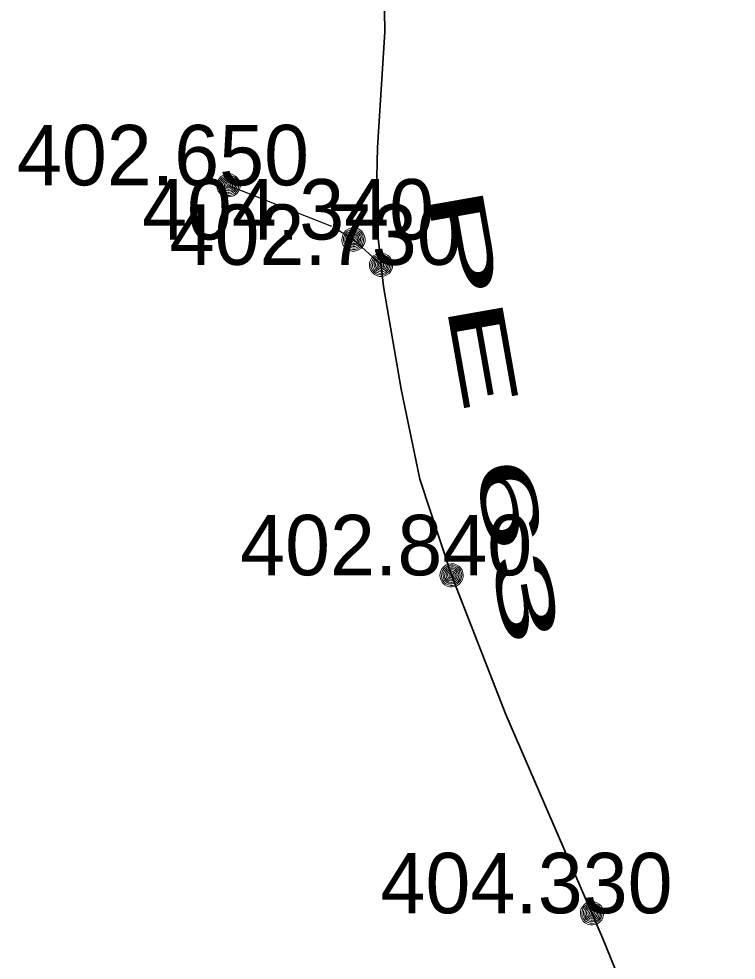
# Model space of a CAD drawing. Extents: x -873619 to -867639, y -1015082 to -1012326.
# Drawn here: x -868003.92 to -867989.67, y -1012758.26 to -1012739.57 of the extents above; entities that cross this region are included whole.
import ezdxf

# ---------------------------------------------------------------- set-up
doc = ezdxf.new("R2010")
doc.units = 0
doc.header["$LTSCALE"] = 0.44
doc.header["$PDMODE"] = 32
doc.header["$PDSIZE"] = 0.22
doc.linetypes.add('DOT_DASHED', pattern=[7.7, 5, -1.2, 0.3, -1.2])
for name, color, linetype, lineweight in [('1', 7, 'Continuous', 13), ('21', 7, 'Continuous', 35), ('23', 7, 'Continuous', 25)]:
    doc.layers.add(name, color=color, linetype=linetype, lineweight=lineweight)
doc.layers.add('33', color=7, linetype='Continuous')

msp = doc.modelspace()

# ---------------------------------------------------------------- linework, layer by layer
at = {"layer": '1'}
for points in [[(-867999.527, -1012742.879), (-867999.534, -1012742.827), (-867999.551, -1012742.777), (-867999.58, -1012742.733), (-867999.617, -1012742.696), (-867999.662, -1012742.669), (-867999.712, -1012742.652), (-867999.765, -1012742.648), (-867999.816, -1012742.655), (-867999.865, -1012742.674), (-867999.909, -1012742.703), (-867999.945, -1012742.742), (-867999.971, -1012742.787), (-867999.987, -1012742.838), (-867999.99, -1012742.89), (-867999.982, -1012742.942), (-867999.962, -1012742.991), (-867999.931, -1012743.034), (-867999.892, -1012743.068), (-867999.846, -1012743.094), (-867999.794, -1012743.108), (-867999.742, -1012743.11), (-867999.691, -1012743.1), (-867999.642, -1012743.079), (-867999.6, -1012743.048), (-867999.566, -1012743.007), (-867999.542, -1012742.961), (-867999.529, -1012742.91)], [(-867999.558, -1012742.879), (-867999.564, -1012742.83), (-867999.581, -1012742.784), (-867999.608, -1012742.744), (-867999.646, -1012742.712), (-867999.69, -1012742.69), (-867999.738, -1012742.679), (-867999.787, -1012742.679), (-867999.833, -1012742.692), (-867999.877, -1012742.716), (-867999.913, -1012742.749), (-867999.94, -1012742.79), (-867999.956, -1012742.837), (-867999.96, -1012742.886), (-867999.953, -1012742.934), (-867999.934, -1012742.979), (-867999.904, -1012743.019), (-867999.865, -1012743.05), (-867999.821, -1012743.07), (-867999.774, -1012743.08), (-867999.725, -1012743.078), (-867999.678, -1012743.063), (-867999.635, -1012743.038), (-867999.6, -1012743.004), (-867999.575, -1012742.962), (-867999.561, -1012742.915)], [(-867999.588, -1012742.879), (-867999.593, -1012742.834), (-867999.61, -1012742.792), (-867999.639, -1012742.757), (-867999.674, -1012742.73), (-867999.717, -1012742.713), (-867999.762, -1012742.708), (-867999.806, -1012742.714), (-867999.848, -1012742.733), (-867999.882, -1012742.761), (-867999.909, -1012742.798), (-867999.926, -1012742.84), (-867999.929, -1012742.885), (-867999.923, -1012742.93), (-867999.904, -1012742.971), (-867999.875, -1012743.005), (-867999.838, -1012743.031), (-867999.794, -1012743.047), (-867999.75, -1012743.05), (-867999.705, -1012743.042), (-867999.664, -1012743.022), (-867999.63, -1012742.993), (-867999.605, -1012742.955), (-867999.591, -1012742.912)], [(-867999.618, -1012742.879), (-867999.622, -1012742.838), (-867999.641, -1012742.801), (-867999.668, -1012742.77), (-867999.703, -1012742.749), (-867999.743, -1012742.738), (-867999.784, -1012742.74), (-867999.823, -1012742.753), (-867999.857, -1012742.777), (-867999.882, -1012742.809), (-867999.897, -1012742.847), (-867999.899, -1012742.888), (-867999.892, -1012742.928), (-867999.872, -1012742.964), (-867999.843, -1012742.993), (-867999.806, -1012743.012), (-867999.766, -1012743.02), (-867999.725, -1012743.016), (-867999.686, -1012743.001), (-867999.654, -1012742.975), (-867999.632, -1012742.941), (-867999.619, -1012742.902)], [(-867999.647, -1012742.879), (-867999.652, -1012742.843), (-867999.671, -1012742.811), (-867999.696, -1012742.786), (-867999.73, -1012742.771), (-867999.767, -1012742.768), (-867999.801, -1012742.776), (-867999.833, -1012742.796), (-867999.855, -1012742.824), (-867999.869, -1012742.858), (-867999.869, -1012742.895), (-867999.858, -1012742.93), (-867999.837, -1012742.959), (-867999.806, -1012742.98), (-867999.772, -1012742.99), (-867999.735, -1012742.988), (-867999.701, -1012742.974), (-867999.674, -1012742.951), (-867999.654, -1012742.919), (-867999.647, -1012742.884)], [(-867999.678, -1012742.879), (-867999.683, -1012742.848), (-867999.7, -1012742.822), (-867999.725, -1012742.805), (-867999.755, -1012742.798), (-867999.787, -1012742.802), (-867999.814, -1012742.819), (-867999.831, -1012742.843), (-867999.84, -1012742.874), (-867999.836, -1012742.904), (-867999.821, -1012742.932), (-867999.796, -1012742.951), (-867999.767, -1012742.96), (-867999.735, -1012742.957), (-867999.708, -1012742.943), (-867999.688, -1012742.919), (-867999.678, -1012742.89)], [(-867999.708, -1012742.879), (-867999.713, -1012742.855), (-867999.73, -1012742.837), (-867999.752, -1012742.828), (-867999.777, -1012742.831), (-867999.798, -1012742.845), (-867999.809, -1012742.867), (-867999.809, -1012742.892), (-867999.796, -1012742.913), (-867999.777, -1012742.927), (-867999.752, -1012742.93), (-867999.728, -1012742.921), (-867999.713, -1012742.903)], [(-867999.738, -1012742.879), (-867999.743, -1012742.864), (-867999.757, -1012742.858), (-867999.772, -1012742.862), (-867999.779, -1012742.876), (-867999.776, -1012742.891), (-867999.762, -1012742.9), (-867999.747, -1012742.897), (-867999.738, -1012742.885)], [(-867997.044, -1012743.954), (-867997.05, -1012743.902), (-867997.067, -1012743.852), (-867997.096, -1012743.808), (-867997.133, -1012743.771), (-867997.178, -1012743.744), (-867997.228, -1012743.727), (-867997.281, -1012743.723), (-867997.333, -1012743.73), (-867997.382, -1012743.749), (-867997.425, -1012743.778), (-867997.461, -1012743.817), (-867997.487, -1012743.862), (-867997.503, -1012743.913), (-867997.506, -1012743.965), (-867997.498, -1012744.017), (-867997.478, -1012744.066), (-867997.447, -1012744.109), (-867997.408, -1012744.143), (-867997.362, -1012744.169), (-867997.311, -1012744.183), (-867997.258, -1012744.185), (-867997.207, -1012744.175), (-867997.159, -1012744.154), (-867997.116, -1012744.123), (-867997.082, -1012744.082), (-867997.058, -1012744.036), (-867997.046, -1012743.985)], [(-867997.074, -1012743.954), (-867997.08, -1012743.905), (-867997.097, -1012743.859), (-867997.125, -1012743.819), (-867997.162, -1012743.787), (-867997.206, -1012743.765), (-867997.254, -1012743.754), (-867997.303, -1012743.754), (-867997.35, -1012743.767), (-867997.393, -1012743.791), (-867997.429, -1012743.824), (-867997.456, -1012743.865), (-867997.472, -1012743.912), (-867997.476, -1012743.961), (-867997.469, -1012744.009), (-867997.45, -1012744.054), (-867997.42, -1012744.094), (-867997.382, -1012744.125), (-867997.338, -1012744.145), (-867997.29, -1012744.155), (-867997.241, -1012744.153), (-867997.194, -1012744.138), (-867997.151, -1012744.113), (-867997.117, -1012744.079), (-867997.091, -1012744.037), (-867997.077, -1012743.99)], [(-867997.104, -1012743.954), (-867997.11, -1012743.909), (-867997.127, -1012743.867), (-867997.155, -1012743.832), (-867997.191, -1012743.805), (-867997.233, -1012743.788), (-867997.278, -1012743.783), (-867997.323, -1012743.789), (-867997.364, -1012743.808), (-867997.399, -1012743.836), (-867997.426, -1012743.873), (-867997.442, -1012743.915), (-867997.446, -1012743.96), (-867997.439, -1012744.005), (-867997.42, -1012744.046), (-867997.391, -1012744.08), (-867997.354, -1012744.106), (-867997.311, -1012744.122), (-867997.266, -1012744.125), (-867997.221, -1012744.117), (-867997.181, -1012744.097), (-867997.147, -1012744.068), (-867997.121, -1012744.03), (-867997.107, -1012743.987)], [(-867997.134, -1012743.954), (-867997.139, -1012743.913), (-867997.157, -1012743.876), (-867997.184, -1012743.845), (-867997.219, -1012743.824), (-867997.259, -1012743.813), (-867997.3, -1012743.815), (-867997.339, -1012743.828), (-867997.373, -1012743.852), (-867997.398, -1012743.884), (-867997.413, -1012743.922), (-867997.416, -1012743.963), (-867997.408, -1012744.003), (-867997.388, -1012744.039), (-867997.359, -1012744.068), (-867997.322, -1012744.087), (-867997.282, -1012744.095), (-867997.241, -1012744.091), (-867997.203, -1012744.076), (-867997.171, -1012744.05), (-867997.148, -1012744.016), (-867997.135, -1012743.977)], [(-867997.164, -1012743.954), (-867997.169, -1012743.918), (-867997.187, -1012743.886), (-867997.213, -1012743.861), (-867997.247, -1012743.846), (-867997.283, -1012743.843), (-867997.318, -1012743.851), (-867997.349, -1012743.871), (-867997.372, -1012743.899), (-867997.385, -1012743.933), (-867997.385, -1012743.97), (-867997.374, -1012744.005), (-867997.353, -1012744.034), (-867997.323, -1012744.055), (-867997.288, -1012744.065), (-867997.251, -1012744.063), (-867997.217, -1012744.049), (-867997.19, -1012744.026), (-867997.171, -1012743.994), (-867997.164, -1012743.959)], [(-867997.194, -1012743.954), (-867997.199, -1012743.923), (-867997.216, -1012743.897), (-867997.242, -1012743.88), (-867997.272, -1012743.873), (-867997.303, -1012743.877), (-867997.33, -1012743.894), (-867997.348, -1012743.918), (-867997.356, -1012743.949), (-867997.352, -1012743.979), (-867997.337, -1012744.007), (-867997.313, -1012744.026), (-867997.283, -1012744.035), (-867997.252, -1012744.032), (-867997.224, -1012744.018), (-867997.204, -1012743.994), (-867997.194, -1012743.965)], [(-867997.224, -1012743.954), (-867997.229, -1012743.93), (-867997.246, -1012743.912), (-867997.269, -1012743.903), (-867997.293, -1012743.906), (-867997.314, -1012743.92), (-867997.325, -1012743.942), (-867997.325, -1012743.967), (-867997.313, -1012743.988), (-867997.293, -1012744.002), (-867997.268, -1012744.005), (-867997.245, -1012743.996), (-867997.229, -1012743.978)], [(-867997.254, -1012743.954), (-867997.259, -1012743.939), (-867997.274, -1012743.933), (-867997.289, -1012743.937), (-867997.296, -1012743.951), (-867997.292, -1012743.966), (-867997.279, -1012743.975), (-867997.264, -1012743.972), (-867997.254, -1012743.96)], [(-867996.495, -1012744.457), (-867996.502, -1012744.405), (-867996.519, -1012744.355), (-867996.548, -1012744.311), (-867996.585, -1012744.274), (-867996.63, -1012744.247), (-867996.679, -1012744.23), (-867996.733, -1012744.226), (-867996.784, -1012744.233), (-867996.833, -1012744.252), (-867996.877, -1012744.281), (-867996.913, -1012744.32), (-867996.939, -1012744.365), (-867996.955, -1012744.416), (-867996.958, -1012744.468), (-867996.95, -1012744.52), (-867996.929, -1012744.569), (-867996.899, -1012744.612), (-867996.86, -1012744.646), (-867996.814, -1012744.672), (-867996.762, -1012744.686), (-867996.71, -1012744.688), (-867996.659, -1012744.678), (-867996.61, -1012744.657), (-867996.568, -1012744.626), (-867996.534, -1012744.585), (-867996.51, -1012744.539), (-867996.497, -1012744.488)], [(-867996.526, -1012744.457), (-867996.532, -1012744.408), (-867996.549, -1012744.362), (-867996.576, -1012744.322), (-867996.614, -1012744.29), (-867996.657, -1012744.268), (-867996.706, -1012744.257), (-867996.755, -1012744.257), (-867996.801, -1012744.27), (-867996.845, -1012744.294), (-867996.88, -1012744.327), (-867996.907, -1012744.368), (-867996.924, -1012744.415), (-867996.928, -1012744.464), (-867996.921, -1012744.512), (-867996.902, -1012744.557), (-867996.872, -1012744.597), (-867996.833, -1012744.628), (-867996.789, -1012744.648), (-867996.742, -1012744.658), (-867996.693, -1012744.656), (-867996.646, -1012744.641), (-867996.603, -1012744.616), (-867996.568, -1012744.582), (-867996.543, -1012744.54), (-867996.529, -1012744.493)], [(-867996.556, -1012744.457), (-867996.561, -1012744.412), (-867996.578, -1012744.37), (-867996.607, -1012744.335), (-867996.642, -1012744.308), (-867996.684, -1012744.291), (-867996.73, -1012744.286), (-867996.774, -1012744.292), (-867996.816, -1012744.311), (-867996.85, -1012744.339), (-867996.877, -1012744.376), (-867996.894, -1012744.418), (-867996.897, -1012744.463), (-867996.891, -1012744.508), (-867996.872, -1012744.549), (-867996.843, -1012744.583), (-867996.806, -1012744.609), (-867996.762, -1012744.625), (-867996.718, -1012744.628), (-867996.673, -1012744.62), (-867996.632, -1012744.6), (-867996.598, -1012744.571), (-867996.573, -1012744.533), (-867996.559, -1012744.49)], [(-867996.586, -1012744.457), (-867996.59, -1012744.416), (-867996.608, -1012744.379), (-867996.636, -1012744.348), (-867996.671, -1012744.327), (-867996.711, -1012744.316), (-867996.752, -1012744.318), (-867996.791, -1012744.331), (-867996.825, -1012744.355), (-867996.85, -1012744.387), (-867996.865, -1012744.425), (-867996.867, -1012744.466), (-867996.86, -1012744.506), (-867996.84, -1012744.542), (-867996.811, -1012744.571), (-867996.774, -1012744.59), (-867996.733, -1012744.598), (-867996.693, -1012744.594), (-867996.654, -1012744.579), (-867996.622, -1012744.553), (-867996.6, -1012744.519), (-867996.587, -1012744.48)], [(-867996.615, -1012744.457), (-867996.62, -1012744.421), (-867996.639, -1012744.389), (-867996.664, -1012744.364), (-867996.698, -1012744.349), (-867996.735, -1012744.346), (-867996.769, -1012744.354), (-867996.801, -1012744.374), (-867996.823, -1012744.402), (-867996.837, -1012744.436), (-867996.837, -1012744.473), (-867996.826, -1012744.508), (-867996.804, -1012744.537), (-867996.774, -1012744.558), (-867996.74, -1012744.568), (-867996.703, -1012744.566), (-867996.669, -1012744.552), (-867996.642, -1012744.529), (-867996.622, -1012744.497), (-867996.615, -1012744.462)], [(-867996.646, -1012744.457), (-867996.651, -1012744.426), (-867996.668, -1012744.4), (-867996.693, -1012744.383), (-867996.723, -1012744.376), (-867996.755, -1012744.38), (-867996.782, -1012744.397), (-867996.799, -1012744.421), (-867996.808, -1012744.452), (-867996.804, -1012744.482), (-867996.789, -1012744.51), (-867996.764, -1012744.529), (-867996.735, -1012744.538), (-867996.703, -1012744.535), (-867996.676, -1012744.521), (-867996.656, -1012744.497), (-867996.646, -1012744.468)], [(-867996.676, -1012744.457), (-867996.681, -1012744.433), (-867996.698, -1012744.415), (-867996.72, -1012744.406), (-867996.745, -1012744.409), (-867996.766, -1012744.423), (-867996.777, -1012744.445), (-867996.777, -1012744.47), (-867996.764, -1012744.491), (-867996.745, -1012744.505), (-867996.72, -1012744.508), (-867996.696, -1012744.499), (-867996.681, -1012744.481)], [(-867996.706, -1012744.457), (-867996.711, -1012744.442), (-867996.725, -1012744.436), (-867996.74, -1012744.44), (-867996.747, -1012744.454), (-867996.744, -1012744.469), (-867996.73, -1012744.478), (-867996.715, -1012744.475), (-867996.706, -1012744.463)], [(-867995.095, -1012750.622), (-867995.101, -1012750.57), (-867995.118, -1012750.52), (-867995.147, -1012750.476), (-867995.184, -1012750.439), (-867995.229, -1012750.412), (-867995.279, -1012750.395), (-867995.332, -1012750.391), (-867995.384, -1012750.398), (-867995.433, -1012750.417), (-867995.476, -1012750.446), (-867995.512, -1012750.485), (-867995.538, -1012750.53), (-867995.554, -1012750.581), (-867995.557, -1012750.633), (-867995.549, -1012750.685), (-867995.529, -1012750.734), (-867995.498, -1012750.777), (-867995.459, -1012750.811), (-867995.413, -1012750.837), (-867995.362, -1012750.851), (-867995.309, -1012750.853), (-867995.258, -1012750.843), (-867995.21, -1012750.822), (-867995.167, -1012750.791), (-867995.133, -1012750.75), (-867995.109, -1012750.704), (-867995.097, -1012750.653)], [(-867995.125, -1012750.622), (-867995.131, -1012750.573), (-867995.148, -1012750.527), (-867995.176, -1012750.487), (-867995.213, -1012750.455), (-867995.257, -1012750.433), (-867995.305, -1012750.422), (-867995.354, -1012750.422), (-867995.401, -1012750.435), (-867995.444, -1012750.459), (-867995.48, -1012750.492), (-867995.507, -1012750.533), (-867995.523, -1012750.58), (-867995.527, -1012750.629), (-867995.52, -1012750.677), (-867995.501, -1012750.722), (-867995.471, -1012750.762), (-867995.433, -1012750.793), (-867995.389, -1012750.813), (-867995.341, -1012750.823), (-867995.292, -1012750.821), (-867995.245, -1012750.806), (-867995.202, -1012750.781), (-867995.168, -1012750.747), (-867995.142, -1012750.705), (-867995.128, -1012750.658)], [(-867995.155, -1012750.622), (-867995.161, -1012750.577), (-867995.178, -1012750.535), (-867995.206, -1012750.5), (-867995.242, -1012750.473), (-867995.284, -1012750.456), (-867995.329, -1012750.451), (-867995.374, -1012750.457), (-867995.415, -1012750.476), (-867995.45, -1012750.504), (-867995.477, -1012750.541), (-867995.493, -1012750.583), (-867995.497, -1012750.628), (-867995.49, -1012750.673), (-867995.471, -1012750.714), (-867995.442, -1012750.748), (-867995.405, -1012750.774), (-867995.362, -1012750.79), (-867995.317, -1012750.793), (-867995.272, -1012750.785), (-867995.232, -1012750.765), (-867995.198, -1012750.736), (-867995.172, -1012750.698), (-867995.158, -1012750.655)], [(-867995.185, -1012750.622), (-867995.19, -1012750.581), (-867995.208, -1012750.544), (-867995.235, -1012750.513), (-867995.27, -1012750.492), (-867995.31, -1012750.481), (-867995.351, -1012750.483), (-867995.39, -1012750.496), (-867995.424, -1012750.52), (-867995.449, -1012750.552), (-867995.464, -1012750.59), (-867995.467, -1012750.631), (-867995.459, -1012750.671), (-867995.439, -1012750.707), (-867995.41, -1012750.736), (-867995.373, -1012750.755), (-867995.333, -1012750.763), (-867995.292, -1012750.759), (-867995.254, -1012750.744), (-867995.222, -1012750.718), (-867995.199, -1012750.684), (-867995.186, -1012750.645)], [(-867995.215, -1012750.622), (-867995.22, -1012750.586), (-867995.238, -1012750.554), (-867995.264, -1012750.529), (-867995.298, -1012750.514), (-867995.334, -1012750.511), (-867995.369, -1012750.519), (-867995.4, -1012750.539), (-867995.423, -1012750.567), (-867995.436, -1012750.601), (-867995.436, -1012750.638), (-867995.425, -1012750.673), (-867995.404, -1012750.702), (-867995.374, -1012750.723), (-867995.339, -1012750.733), (-867995.302, -1012750.731), (-867995.268, -1012750.717), (-867995.241, -1012750.694), (-867995.222, -1012750.662), (-867995.215, -1012750.627)], [(-867995.245, -1012750.622), (-867995.25, -1012750.591), (-867995.267, -1012750.565), (-867995.293, -1012750.548), (-867995.323, -1012750.541), (-867995.354, -1012750.545), (-867995.381, -1012750.562), (-867995.399, -1012750.586), (-867995.407, -1012750.617), (-867995.403, -1012750.647), (-867995.388, -1012750.675), (-867995.364, -1012750.694), (-867995.334, -1012750.703), (-867995.303, -1012750.7), (-867995.275, -1012750.686), (-867995.255, -1012750.662), (-867995.245, -1012750.633)], [(-867995.275, -1012750.622), (-867995.28, -1012750.598), (-867995.297, -1012750.58), (-867995.32, -1012750.571), (-867995.344, -1012750.574), (-867995.365, -1012750.588), (-867995.376, -1012750.61), (-867995.376, -1012750.635), (-867995.364, -1012750.656), (-867995.344, -1012750.67), (-867995.319, -1012750.673), (-867995.296, -1012750.664), (-867995.28, -1012750.646)], [(-867995.305, -1012750.622), (-867995.31, -1012750.607), (-867995.325, -1012750.601), (-867995.34, -1012750.605), (-867995.347, -1012750.619), (-867995.343, -1012750.634), (-867995.33, -1012750.643), (-867995.315, -1012750.64), (-867995.305, -1012750.628)], [(-867992.306, -1012757.333), (-867992.313, -1012757.281), (-867992.33, -1012757.231), (-867992.358, -1012757.187), (-867992.396, -1012757.15), (-867992.441, -1012757.123), (-867992.49, -1012757.106), (-867992.544, -1012757.102), (-867992.595, -1012757.109), (-867992.644, -1012757.128), (-867992.688, -1012757.157), (-867992.723, -1012757.196), (-867992.75, -1012757.241), (-867992.766, -1012757.292), (-867992.769, -1012757.344), (-867992.761, -1012757.396), (-867992.74, -1012757.445), (-867992.71, -1012757.488), (-867992.671, -1012757.522), (-867992.625, -1012757.548), (-867992.573, -1012757.562), (-867992.521, -1012757.564), (-867992.47, -1012757.554), (-867992.421, -1012757.533), (-867992.379, -1012757.502), (-867992.345, -1012757.461), (-867992.321, -1012757.415), (-867992.308, -1012757.364)], [(-867992.337, -1012757.333), (-867992.343, -1012757.284), (-867992.36, -1012757.238), (-867992.387, -1012757.198), (-867992.424, -1012757.166), (-867992.468, -1012757.144), (-867992.517, -1012757.133), (-867992.566, -1012757.133), (-867992.612, -1012757.146), (-867992.656, -1012757.17), (-867992.691, -1012757.203), (-867992.718, -1012757.244), (-867992.735, -1012757.291), (-867992.739, -1012757.34), (-867992.732, -1012757.388), (-867992.713, -1012757.433), (-867992.683, -1012757.473), (-867992.644, -1012757.504), (-867992.6, -1012757.524), (-867992.553, -1012757.534), (-867992.504, -1012757.532), (-867992.456, -1012757.517), (-867992.414, -1012757.492), (-867992.379, -1012757.458), (-867992.353, -1012757.416), (-867992.34, -1012757.369)], [(-867992.367, -1012757.333), (-867992.372, -1012757.288), (-867992.389, -1012757.246), (-867992.418, -1012757.211), (-867992.453, -1012757.184), (-867992.495, -1012757.167), (-867992.541, -1012757.162), (-867992.585, -1012757.168), (-867992.627, -1012757.187), (-867992.661, -1012757.215), (-867992.688, -1012757.252), (-867992.705, -1012757.294), (-867992.708, -1012757.339), (-867992.701, -1012757.384), (-867992.683, -1012757.425), (-867992.654, -1012757.459), (-867992.617, -1012757.485), (-867992.573, -1012757.501), (-867992.529, -1012757.504), (-867992.483, -1012757.496), (-867992.443, -1012757.476), (-867992.409, -1012757.447), (-867992.384, -1012757.409), (-867992.37, -1012757.366)], [(-867992.397, -1012757.333), (-867992.401, -1012757.292), (-867992.419, -1012757.255), (-867992.446, -1012757.224), (-867992.482, -1012757.203), (-867992.522, -1012757.192), (-867992.563, -1012757.194), (-867992.602, -1012757.207), (-867992.636, -1012757.231), (-867992.661, -1012757.263), (-867992.676, -1012757.301), (-867992.678, -1012757.342), (-867992.671, -1012757.382), (-867992.651, -1012757.418), (-867992.622, -1012757.447), (-867992.585, -1012757.466), (-867992.544, -1012757.474), (-867992.504, -1012757.47), (-867992.465, -1012757.455), (-867992.433, -1012757.429), (-867992.411, -1012757.395), (-867992.397, -1012757.356)], [(-867992.426, -1012757.333), (-867992.431, -1012757.297), (-867992.45, -1012757.265), (-867992.475, -1012757.24), (-867992.509, -1012757.225), (-867992.546, -1012757.222), (-867992.58, -1012757.23), (-867992.612, -1012757.25), (-867992.634, -1012757.278), (-867992.647, -1012757.312), (-867992.647, -1012757.349), (-867992.637, -1012757.384), (-867992.615, -1012757.413), (-867992.585, -1012757.434), (-867992.551, -1012757.444), (-867992.514, -1012757.442), (-867992.48, -1012757.428), (-867992.453, -1012757.405), (-867992.433, -1012757.373), (-867992.426, -1012757.338)], [(-867992.456, -1012757.333), (-867992.462, -1012757.302), (-867992.478, -1012757.276), (-867992.504, -1012757.259), (-867992.534, -1012757.252), (-867992.566, -1012757.256), (-867992.593, -1012757.273), (-867992.61, -1012757.297), (-867992.619, -1012757.328), (-867992.615, -1012757.358), (-867992.6, -1012757.386), (-867992.575, -1012757.405), (-867992.546, -1012757.414), (-867992.514, -1012757.411), (-867992.487, -1012757.397), (-867992.467, -1012757.373), (-867992.456, -1012757.344)], [(-867992.487, -1012757.333), (-867992.492, -1012757.309), (-867992.509, -1012757.291), (-867992.531, -1012757.282), (-867992.556, -1012757.285), (-867992.576, -1012757.299), (-867992.588, -1012757.321), (-867992.588, -1012757.346), (-867992.575, -1012757.367), (-867992.556, -1012757.381), (-867992.531, -1012757.384), (-867992.507, -1012757.375), (-867992.492, -1012757.357)], [(-867992.517, -1012757.333), (-867992.522, -1012757.318), (-867992.536, -1012757.312), (-867992.551, -1012757.316), (-867992.558, -1012757.33), (-867992.554, -1012757.345), (-867992.541, -1012757.354), (-867992.526, -1012757.351), (-867992.517, -1012757.339)]]:
    msp.add_lwpolyline(points, close=True, dxfattribs=at)
at = {"layer": '21'}
msp.add_lwpolyline([(-867994.551, -1012718.479), (-867999.799, -1012726.127), (-867998.71, -1012729.979), (-867996.966, -1012736.043), (-867996.742, -1012736.964), (-867996.7, -1012737.662), (-867996.679, -1012738.122), (-867996.65, -1012739.832), (-867996.798, -1012742.128), (-867996.826, -1012743.328), (-867996.837, -1012743.442), (-867996.68, -1012744.886), (-867996.331, -1012746.924), (-867995.954, -1012748.71), (-867995.326, -1012750.622), (-867994.252, -1012753.385), (-867992.326, -1012757.823), (-867989.674, -1012764.355)], dxfattribs=at)
at = {"layer": '23', "linetype": 'DOT_DASHED'}
msp.add_lwpolyline([(-867999.759, -1012742.879), (-867997.679, -1012743.703), (-867997.275, -1012743.954), (-867996.727, -1012744.457)], dxfattribs=at)
at = {"layer": '33'}
msp.add_point((-867997.275, -1012743.954), dxfattribs=at)

# ---------------------------------------------------------------- texts
at = {"layer": '1'}
for s, p in [('402.650 ', (-868003.959, -1012742.879)), ('404.340 ', (-868001.475, -1012743.954)), ('402.730 ', (-868000.927, -1012744.457)), ('402.840 ', (-867999.526, -1012750.622)), ('404.330 ', (-867996.738, -1012757.333))]:
    msp.add_text(s, height=1.2, dxfattribs=at).set_placement(p)
at = {"layer": '1', "width": 2.3}
msp.add_text('PE 63 ', height=1.1, rotation=280, dxfattribs=at).set_placement((-867995.836, -1012743))

doc.saveas('drawing.dxf')
